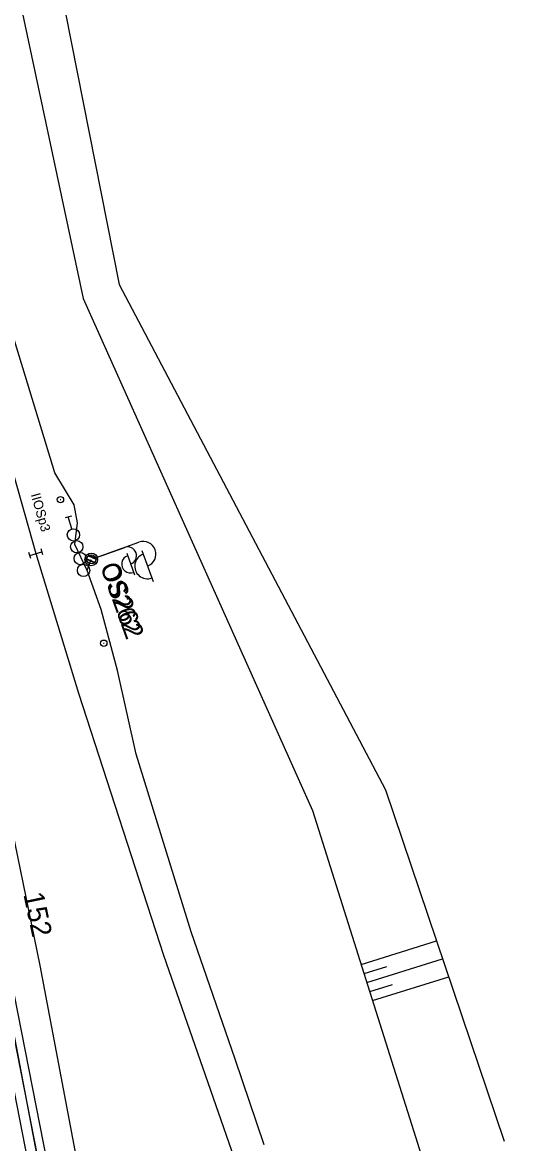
# Model space of a CAD drawing. Extents: x -545967 to -545044, y -1122650 to -1118491.
# Drawn here: x -545731.6 to -545693, y -1119096.1 to -1119007.5 of the extents above; entities that cross this region are included whole.
import ezdxf

# ---------------------------------------------------------------- set-up
doc = ezdxf.new("R2010")
doc.units = 0
for name, color, linetype in [('Vrstva 1', 7, 'Continuous'), ('Vrstva 11 - Trakce', 7, 'Continuous'), ('Vrstva 25', 7, 'Continuous'), ('Vrstva 25 - silnoproud prvky', 7, 'Continuous'), ('Vrstva 26', 7, 'Continuous'), ('Vrstva 26 - silnoproud', 7, 'Continuous'), ('Vrstva 28', 7, 'Continuous'), ('Vrstva 3', 7, 'Continuous'), ('Vrstva 4 - Teren - stezky - prechody - plochy', 7, 'Continuous'), ('Vrstva 44', 7, 'Continuous'), ('Vrstva 48', 7, 'Continuous'), ('Vrstva 49', 7, 'Continuous'), ('Vrstva 50', 7, 'Continuous'), ('Vrstva 6', 7, 'Continuous')]:
    doc.layers.add(name, color=color, linetype=linetype)

msp = doc.modelspace()

# ---------------------------------------------------------------- linework, layer by layer
at = {"layer": 'Vrstva 1'}
for points in [[(-545803.343, -1118697.361), (-545802.529, -1118701.559), (-545796.372, -1118733.137), (-545788.892, -1118771.626), (-545784.123, -1118796.192), (-545777.723, -1118829.089), (-545771.163, -1118862.699), (-545764.792, -1118895.381), (-545757.603, -1118932.309), (-545753.441, -1118953.648), (-545749.904, -1118971.286), (-545746.403, -1118987.4), (-545742.64, -1119003.664), (-545739.307, -1119017.411), (-545735.997, -1119030.103), (-545730.526, -1119049.438)], [(-545730.526, -1119049.438), (-545727.173, -1119060.47), (-545720.468, -1119081.174), (-545711.793, -1119106.078), (-545703.851, -1119128.397), (-545698.023, -1119144.665), (-545693.948, -1119156.135), (-545691.544, -1119162.895), (-545690.154, -1119166.896), (-545689.961, -1119167.438), (-545689.699, -1119168.179), (-545684.737, -1119182.215), (-545679.147, -1119198.024), (-545676.369, -1119205.846), (-545670.918, -1119221.162), (-545664.828, -1119238.335)]]:
    msp.add_lwpolyline(points, dxfattribs=at)
at = {"layer": 'Vrstva 25'}
for p, q in [((-545725.684, -1119049.729), (-545722.39, -1119048.546)), ((-545726.647, -1119049.821), (-545725.781, -1119050.229)), ((-545726.454, -1119049.497), (-545725.658, -1119049.873)), ((-545722.154, -1119049.205), (-545721.275, -1119051.652))]:
    msp.add_line(p, q, dxfattribs=at)
msp.add_circle((-545726.155, -1119049.898), 0.5, dxfattribs=at)
msp.add_circle((-545726.155, -1119049.898), 0.5, dxfattribs=at)
for centre, start, end in [((-545722.052, -1119049.487), 289.75658, 109.75658), ((-545721.726, -1119050.432), 109.05401, 290.45916)]:
    msp.add_arc(centre, 1, start, end, dxfattribs=at)
at = {"layer": 'Vrstva 25 - silnoproud prvky'}
for p, q in [((-545725.826, -1119049.78), (-545723.52, -1119048.952)), ((-545726.499, -1119049.844), (-545725.893, -1119050.13)), ((-545726.364, -1119049.618), (-545725.807, -1119049.88)), ((-545723.354, -1119049.413), (-545722.739, -1119051.126))]:
    msp.add_line(p, q, dxfattribs=at)
msp.add_circle((-545726.155, -1119049.898), 0.35, dxfattribs=at)
for centre, start, end in [((-545723.283, -1119049.61), 289.75658, 109.75658), ((-545723.055, -1119050.272), 109.05401, 290.45916)]:
    msp.add_arc(centre, 0.7, start, end, dxfattribs=at)
at = {"layer": 'Vrstva 26'}
for points in [[(-545712.501, -1119096.161), (-545714.801, -1119089.398), (-545718.283, -1119079.346), (-545722.619, -1119065.292), (-545724.086, -1119058.686), (-545725.374, -1119053.847), (-545726.477, -1119050.776), (-545727.447, -1119048.729), (-545727.234, -1119047.022), (-545727.52, -1119045.588), (-545729.026, -1119043.068), (-545733.358, -1119028.888), (-545737.609, -1119013.08), (-545738.971, -1119007.186), (-545740.966, -1118998.367), (-545742.1, -1118993.408), (-545744.469, -1118982.238), (-545746.037, -1118973.539), (-545748.64, -1118961.097)], [(-545726.477, -1119050.776), (-545726.155, -1119049.898)]]:
    msp.add_lwpolyline(points, dxfattribs=at)
at = {"layer": 'Vrstva 26 - silnoproud'}
for points in [[(-545712.501, -1119096.161), (-545714.801, -1119089.398), (-545718.283, -1119079.346), (-545722.619, -1119065.292), (-545724.086, -1119058.686), (-545725.374, -1119053.847), (-545726.477, -1119050.776), (-545727.447, -1119048.729), (-545727.234, -1119047.022), (-545727.52, -1119045.588), (-545729.026, -1119043.068), (-545733.358, -1119028.888), (-545737.609, -1119013.08), (-545738.971, -1119007.186), (-545740.966, -1118998.367), (-545742.1, -1118993.408), (-545744.469, -1118982.238), (-545746.037, -1118973.539), (-545748.64, -1118961.097)], [(-545726.477, -1119050.776), (-545726.155, -1119049.898)]]:
    msp.add_lwpolyline(points, dxfattribs=at)
at = {"layer": 'Vrstva 28'}
msp.add_line((-545728.612, -1119045.177), (-545728.562, -1119045.177), dxfattribs=at)
msp.add_circle((-545728.587, -1119045.177), 0.25, dxfattribs=at)
at = {"layer": 'Vrstva 3'}
for p, q in [((-545730.932, -1119049.823), (-545731.077, -1119049.344)), ((-545731.004, -1119049.583), (-545730.048, -1119049.293)), ((-545729.975, -1119049.532), (-545730.12, -1119049.053))]:
    msp.add_line(p, q, dxfattribs=at)
at = {"layer": 'Vrstva 4 - Teren - stezky - prechody - plochy'}
for points in [[(-545842.991, -1118523.919), (-545841.705, -1118530.396), (-545836.849, -1118554.447), (-545831.054, -1118584.604), (-545819.351, -1118645.264), (-545811.232, -1118686.911), (-545799.532, -1118746.647), (-545788.535, -1118802.768), (-545777.847, -1118857.696), (-545765.826, -1118919.341), (-545755.98, -1118970.183), (-545745.509, -1119023.121), (-545734.813, -1119078.883), (-545723.148, -1119138.675), (-545711.327, -1119199.256), (-545707.51, -1119218.932), (-545706.355, -1119218.803)], [(-545787.709, -1118802.92), (-545777.141, -1118857.583), (-545765.122, -1118918.891), (-545755.123, -1118970.549), (-545744.471, -1119024.933), (-545734.117, -1119078.34), (-545722.331, -1119138.405), (-545711.219, -1119196.145), (-545707.543, -1119214.266), (-545707.412, -1119215.197), (-545706.355, -1119218.803)]]:
    msp.add_lwpolyline(points, dxfattribs=at)
at = {"layer": 'Vrstva 44'}
msp.add_lwpolyline([(-545730.081, -1119098.833), (-545737.375, -1119060.454), (-545745.202, -1119020.613), (-545752.526, -1118984.222)], dxfattribs=at)
at = {"layer": 'Vrstva 48'}
for p, q in [((-545704.851, -1119081.908), (-545698.904, -1119080.037)), ((-545704.401, -1119083.339), (-545698.424, -1119081.458)), ((-545704.626, -1119082.624), (-545702.837, -1119082.061)), ((-545704.176, -1119084.054), (-545702.378, -1119083.489)), ((-545703.951, -1119084.77), (-545697.944, -1119082.88))]:
    msp.add_line(p, q, dxfattribs=at)
at = {"layer": 'Vrstva 49'}
for points in [[(-545839.308, -1118523.198), (-545838.102, -1118529.579), (-545837.4, -1118533.485), (-545832.706, -1118555.695), (-545825.144, -1118594.377), (-545814.251, -1118651.352), (-545808.026, -1118685.152), (-545795.162, -1118750.192), (-545783.943, -1118809.71), (-545774.848, -1118856.951), (-545763.418, -1118915.038), (-545752.928, -1118968.655), (-545741.707, -1119025.946), (-545730.219, -1119081.986), (-545719.001, -1119141.326), (-545708.857, -1119196.833), (-545704.642, -1119214.146)], [(-545795.7, -1118699.528), (-545788.233, -1118737.742), (-545783.17, -1118774.198), (-545777.676, -1118791.958), (-545766.252, -1118834.896), (-545762.229, -1118863.517), (-545750.538, -1118910.15), (-545748.755, -1118933.679), (-545738.226, -1118978.242), (-545734.453, -1118993.366), (-545726.802, -1119029.271), (-545708.682, -1119069.733), (-545699.17, -1119099.963), (-545685.313, -1119124.181), (-545683.358, -1119136.056), (-545688.074, -1119145.796), (-545688.341, -1119153.091)], [(-545785.57, -1118809.023), (-545776.461, -1118857.744), (-545776.223, -1118859.028), (-545764.986, -1118916.441), (-545764.658, -1118917.886), (-545754.446, -1118970.66), (-545754.175, -1118971.989), (-545744.319, -1119022.631), (-545744.059, -1119023.95), (-545733.435, -1119078.425), (-545721.625, -1119138.52), (-545721.391, -1119139.742), (-545710.151, -1119197.125), (-545709.969, -1119198.727), (-545706.792, -1119214.135), (-545707.412, -1119215.197), (-545706.355, -1119218.803), (-545705.856, -1119218.828), (-545705.109, -1119218.756), (-545703.505, -1119218.63), (-545703.071, -1119219.321), (-545701.68, -1119223.926)], [(-545740.894, -1118934.351), (-545731.052, -1118992.184), (-545723.951, -1119028.164), (-545702.926, -1119068.123), (-545693.558, -1119095.87)]]:
    msp.add_lwpolyline(points, dxfattribs=at)
at = {"layer": 'Vrstva 50'}
msp.add_line((-545725.191, -1119056.524), (-545725.141, -1119056.524), dxfattribs=at)
msp.add_circle((-545725.166, -1119056.524), 0.25, dxfattribs=at)
at = {"layer": 'Vrstva 6'}
for p, q in [((-545727.728, -1119046.476), (-545728.209, -1119046.612)), ((-545727.698, -1119047.497), (-545727.968, -1119046.545))]:
    msp.add_line(p, q, dxfattribs=at)
for centre in [(-545727.564, -1119047.964), (-545727.299, -1119048.898), (-545727.033, -1119049.832), (-545726.767, -1119050.765)]:
    msp.add_circle(centre, 0.486, dxfattribs=at)

# ---------------------------------------------------------------- texts
at = {"layer": 'Vrstva 11 - Trakce'}
msp.add_text('152', height=1.6, rotation=281.9557, dxfattribs=at).set_placement((-545731.523, -1119076.364))
at = {"layer": 'Vrstva 25'}
msp.add_text('OS262', height=1.5, rotation=289.75658, dxfattribs=at).set_placement((-545725.467, -1119050.455))
at = {"layer": 'Vrstva 25 - silnoproud prvky'}
msp.add_text('OS262', height=1.4, rotation=289.75658, dxfattribs=at).set_placement((-545725.467, -1119050.455))
at = {"layer": 'Vrstva 6'}
msp.add_text('IIOSp3', height=0.75, rotation=285.7993, dxfattribs=at).set_placement((-545730.934, -1119044.777))

doc.saveas('drawing.dxf')
